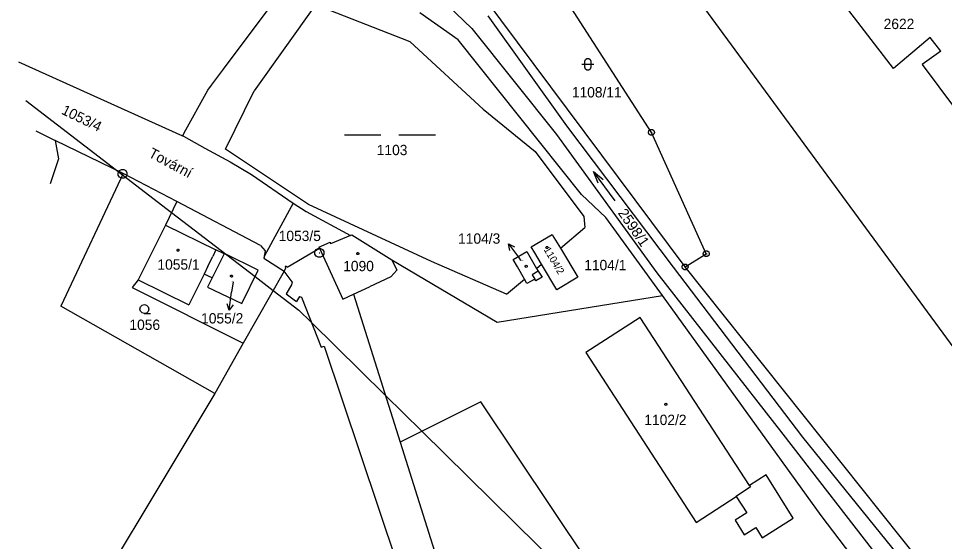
# Model space of a CAD drawing. Extents: x -806774 to -803680, y -1151731 to -1150053.
# Drawn here: x -804231.2 to -804078.6, y -1150279.7 to -1150193.4 of the extents above; entities that cross this region are included whole.
import ezdxf

# ---------------------------------------------------------------- set-up
doc = ezdxf.new("R2010")
doc.units = 0
for name, color, linetype in [('1', 7, 'Continuous'), ('11', 7, 'Continuous'), ('12', 7, 'Continuous'), ('2', 7, 'Continuous'), ('3', 7, 'Continuous'), ('4', 7, 'Continuous'), ('5', 7, 'Continuous'), ('7', 7, 'Continuous'), ('8', 7, 'Continuous')]:
    doc.layers.add(name, color=color, linetype=linetype)

msp = doc.modelspace()

# ---------------------------------------------------------------- linework, layer by layer
at = {"layer": '1'}
for p, q in [((-804126.9, -1150212.23), (-804145.58, -1150183.24)), ((-804197.45, -1150201.82), (-804184.26, -1150184.19)), ((-804121.35, -1150234.4), (-804156.46, -1150187.28)), ((-804087, -1150201.67), (-804097.02, -1150188.64)), ((-804182.27, -1150191.21), (-804192.39, -1150205.34)), ((-804166.66, -1150197.27), (-804182.27, -1150191.21)), ((-804158.76, -1150196.95), (-804165.08, -1150192.52)), ((-804166.66, -1150197.27), (-804154.63, -1150208.39)), ((-804138.44, -1150222.48), (-804158.76, -1150196.95)), ((-804080.94, -1150196.58), (-804087, -1150201.67)), ((-804079.2, -1150198.82), (-804080.94, -1150196.58)), ((-804079.2, -1150198.82), (-804082.27, -1150201.05)), ((-804231.23, -1150200.58), (-804204.2, -1150212.78)), ((-804199.4, -1150204.43), (-804197.45, -1150201.82)), ((-804082.27, -1150201.05), (-804076.76, -1150208.41)), ((-804203.9, -1150212.27), (-804200.03, -1150205.28)), ((-804200.03, -1150205.28), (-804199.4, -1150204.43)), ((-804197.12, -1150214.97), (-804192.39, -1150205.34)), ((-804154.63, -1150208.39), (-804146.05, -1150215.39)), ((-804228.4, -1150211.95), (-804225.21, -1150213.58)), ((-804203.9, -1150212.27), (-804204.2, -1150212.78)), ((-804204.2, -1150212.78), (-804204.05, -1150212.85)), ((-804204.05, -1150212.85), (-804200.51, -1150214.79)), ((-804117.86, -1150232.22), (-804126.9, -1150212.23)), ((-804225.21, -1150213.58), (-804224.63, -1150216.55)), ((-804213.98, -1150218.97), (-804225.21, -1150213.58)), ((-804200.51, -1150214.79), (-804196.34, -1150217.06)), ((-804183.44, -1150224.11), (-804197.12, -1150214.97)), ((-804146.05, -1150215.39), (-804138.03, -1150226.06)), ((-804224.63, -1150216.55), (-804226, -1150220.72)), ((-804196.34, -1150217.06), (-804192.85, -1150219.16)), ((-804213.98, -1150218.97), (-804224.25, -1150240.88)), ((-804205.16, -1150223.61), (-804213.98, -1150218.97)), ((-804192.85, -1150219.16), (-804185.95, -1150223.88)), ((-804205.16, -1150223.61), (-804206.99, -1150227.5)), ((-804191.34, -1150230.88), (-804205.16, -1150223.61)), ((-804134.41, -1150226.23), (-804138.44, -1150222.48)), ((-804185.95, -1150223.88), (-804190.68, -1150232.58)), ((-804185.95, -1150223.88), (-804183.81, -1150225.26)), ((-804183.81, -1150225.26), (-804176.51, -1150229.21)), ((-804163.17, -1150233.5), (-804183.44, -1150224.11)), ((-804138.03, -1150226.06), (-804137.9, -1150227.9)), ((-804125.07, -1150239.09), (-804134.41, -1150226.23)), ((-804206.99, -1150227.5), (-804211.52, -1150236.54)), ((-804141.9, -1150231.32), (-804137.9, -1150227.9)), ((-804176.51, -1150229.21), (-804179.78, -1150230.61)), ((-804176.51, -1150229.21), (-804176.28, -1150229.11)), ((-804176.28, -1150229.11), (-804169.72, -1150233.25)), ((-804146.72, -1150231.08), (-804143.27, -1150229.04)), ((-804143.27, -1150229.04), (-804142.98, -1150229.52)), ((-804142.98, -1150229.52), (-804141.9, -1150231.32)), ((-804191.34, -1150230.88), (-804190.6, -1150231.74)), ((-804186.96, -1150234.45), (-804181.64, -1150231.33)), ((-804181.72, -1150231.15), (-804179.84, -1150230.31)), ((-804181.72, -1150231.15), (-804181.64, -1150231.33)), ((-804181.64, -1150231.33), (-804177.76, -1150239.69)), ((-804179.84, -1150230.31), (-804179.78, -1150230.61)), ((-804146.13, -1150232.06), (-804146.72, -1150231.08)), ((-804141.9, -1150231.32), (-804139.01, -1150236.11)), ((-804197.31, -1150232.21), (-804199.31, -1150236.18)), ((-804197.3, -1150232.19), (-804197.31, -1150232.21)), ((-804191.7, -1150234.93), (-804197.3, -1150232.19)), ((-804190.6, -1150231.74), (-804190.81, -1150232.94)), ((-804190.68, -1150232.58), (-804190.81, -1150232.94)), ((-804149.69, -1150233.15), (-804147.45, -1150231.88)), ((-804147.45, -1150231.88), (-804146.95, -1150232.73)), ((-804146.95, -1150232.73), (-804145.82, -1150234.66)), ((-804145, -1150233.96), (-804146.13, -1150232.06)), ((-804121.35, -1150234.4), (-804117.86, -1150232.22)), ((-804190.81, -1150232.94), (-804187.42, -1150235.07)), ((-804187.1, -1150234.28), (-804187.25, -1150234.4)), ((-804187.25, -1150234.4), (-804187.2, -1150234.6)), ((-804186.96, -1150234.45), (-804187.1, -1150234.28)), ((-804169.72, -1150233.25), (-804168.87, -1150234.95)), ((-804169.72, -1150233.25), (-804152.35, -1150243.49)), ((-804150.79, -1150238.91), (-804163.17, -1150233.5)), ((-804148.99, -1150234.38), (-804149.69, -1150233.15)), ((-804147.85, -1150236.4), (-804148.99, -1150234.38)), ((-804145.82, -1150234.66), (-804145, -1150233.96)), ((-804142.49, -1150238.15), (-804145, -1150233.96)), ((-804081.21, -1150284.7), (-804121.35, -1150234.4)), ((-804194.4, -1150240.45), (-804191.7, -1150234.93)), ((-804187.42, -1150235.07), (-804194.18, -1150246.99)), ((-804187.2, -1150234.6), (-804187.42, -1150235.07)), ((-804186.12, -1150236.84), (-804187.42, -1150235.07)), ((-804168.87, -1150234.95), (-804169.87, -1150236.05)), ((-804145.82, -1150234.66), (-804145.55, -1150235.12)), ((-804145.55, -1150235.12), (-804144.92, -1150236.11)), ((-804211.52, -1150236.54), (-804212.49, -1150237.81)), ((-804199.31, -1150236.18), (-804200.07, -1150237.74)), ((-804186.21, -1150237.35), (-804187.12, -1150238.84)), ((-804186.12, -1150236.84), (-804186.21, -1150237.35)), ((-804169.87, -1150236.05), (-804173.37, -1150237.66)), ((-804150.79, -1150238.91), (-804147.85, -1150236.4)), ((-804147.43, -1150237.14), (-804147.85, -1150236.4)), ((-804146.14, -1150236.42), (-804147.43, -1150237.14)), ((-804145.97, -1150236.71), (-804146.14, -1150236.42)), ((-804144.92, -1150236.11), (-804145.97, -1150236.71)), ((-804139.01, -1150236.11), (-804142.49, -1150238.15)), ((-804212.49, -1150237.81), (-804194.18, -1150246.99)), ((-804200.07, -1150237.74), (-804194.4, -1150240.45)), ((-804187.12, -1150238.84), (-804186.69, -1150239.16)), ((-804177.76, -1150239.69), (-804176.03, -1150238.89)), ((-804176.03, -1150238.89), (-804173.37, -1150237.66)), ((-804176.03, -1150238.89), (-804168.33, -1150263.26)), ((-804186.69, -1150239.16), (-804185.81, -1150239.81)), ((-804185.81, -1150239.81), (-804185.41, -1150240.11)), ((-804184.91, -1150239.25), (-804185.41, -1150240.11)), ((-804184.91, -1150239.25), (-804184.57, -1150239.39)), ((-804184.57, -1150239.39), (-804181.35, -1150247.65)), ((-804152.35, -1150243.49), (-804125.07, -1150239.09)), ((-804098.91, -1150275.35), (-804125.07, -1150239.09)), ((-804198.87, -1150255.25), (-804224.25, -1150240.88)), ((-804128.74, -1150242.73), (-804137.71, -1150248.5)), ((-804110.74, -1150270.45), (-804128.74, -1150242.73)), ((-804194.18, -1150246.99), (-804198.87, -1150255.25)), ((-804181.35, -1150247.65), (-804180.87, -1150247.45)), ((-804180.87, -1150247.45), (-804164.62, -1150295.77)), ((-804137.71, -1150248.5), (-804119.52, -1150276.54)), ((-804198.87, -1150255.25), (-804209.11, -1150272.3)), ((-804155.03, -1150256.65), (-804165.04, -1150261.63)), ((-804116.64, -1150313.9), (-804155.03, -1150256.65)), ((-804165.04, -1150261.63), (-804168.33, -1150263.26)), ((-804168.33, -1150263.26), (-804152.34, -1150313.77)), ((-804108.01, -1150268.68), (-804110.74, -1150270.45)), ((-804103.54, -1150275.84), (-804108.01, -1150268.68)), ((-804209.11, -1150272.3), (-804220.9, -1150291.91)), ((-804119.52, -1150276.54), (-804112.91, -1150272.23)), ((-804112.91, -1150272.23), (-804111.15, -1150274.93)), ((-804111.15, -1150274.93), (-804113.12, -1150276.17)), ((-804036.11, -1150358.19), (-804098.91, -1150275.35)), ((-804113.12, -1150276.17), (-804111.63, -1150278.57)), ((-804108.65, -1150279.08), (-804103.54, -1150275.84)), ((-804111.63, -1150278.57), (-804109.69, -1150277.35)), ((-804109.69, -1150277.35), (-804108.65, -1150279.08))]:
    msp.add_line(p, q, dxfattribs=at)
at = {"layer": '11'}
for points in [[(-804075, -1150250.5), (-804130.24, -1150175.18), (-804140.05, -1150161.79), (-804142.89, -1150157.92)], [(-804230.04, -1150206.98), (-804215.07, -1150218.45), (-804214.09, -1150219.2), (-804206, -1150225.4), (-804196.87, -1150232.4), (-804192.21, -1150235.97), (-804189.23, -1150238.26), (-804185, -1150241.5), (-804182.97, -1150243.51), (-804170.77, -1150255.53), (-804164.74, -1150261.48), (-804126.52, -1150299.17), (-804113, -1150312.5), (-804105.14, -1150321.67), (-804088.1, -1150341.55)]]:
    msp.add_lwpolyline(points, dxfattribs=at)
at = {"layer": '12'}
for p, q in [((-804206.99, -1150227.5), (-804211.52, -1150236.54)), ((-804206.99, -1150227.5), (-804198.68, -1150231.59)), ((-804176.51, -1150229.21), (-804179.78, -1150230.61)), ((-804176.51, -1150229.21), (-804176.28, -1150229.11)), ((-804176.28, -1150229.11), (-804169.72, -1150233.25)), ((-804146.72, -1150231.08), (-804143.27, -1150229.04)), ((-804143.27, -1150229.04), (-804142.98, -1150229.52)), ((-804142.98, -1150229.52), (-804141.9, -1150231.32)), ((-804181.72, -1150231.15), (-804179.84, -1150230.31)), ((-804181.72, -1150231.15), (-804181.64, -1150231.33)), ((-804181.64, -1150231.33), (-804177.76, -1150239.69)), ((-804179.84, -1150230.31), (-804179.78, -1150230.61)), ((-804146.13, -1150232.06), (-804146.72, -1150231.08)), ((-804141.9, -1150231.32), (-804139.01, -1150236.11)), ((-804200, -1150234.26), (-804199.22, -1150232.68)), ((-804197.31, -1150232.21), (-804199.31, -1150236.18)), ((-804198.68, -1150231.59), (-804199.22, -1150232.68)), ((-804197.3, -1150232.19), (-804197.31, -1150232.21)), ((-804191.7, -1150234.93), (-804197.3, -1150232.19)), ((-804149.69, -1150233.15), (-804147.45, -1150231.88)), ((-804147.45, -1150231.88), (-804146.95, -1150232.73)), ((-804146.95, -1150232.73), (-804145.82, -1150234.66)), ((-804145, -1150233.96), (-804146.13, -1150232.06)), ((-804200, -1150234.26), (-804200.64, -1150235.59)), ((-804169.72, -1150233.25), (-804168.87, -1150234.95)), ((-804148.99, -1150234.38), (-804149.69, -1150233.15)), ((-804147.85, -1150236.4), (-804148.99, -1150234.38)), ((-804142.49, -1150238.15), (-804145, -1150233.96)), ((-804200.64, -1150235.59), (-804203.16, -1150240.67)), ((-804194.4, -1150240.45), (-804191.7, -1150234.93)), ((-804168.87, -1150234.95), (-804169.87, -1150236.05)), ((-804145.55, -1150235.12), (-804146.56, -1150235.7)), ((-804146.56, -1150235.7), (-804146.14, -1150236.42)), ((-804145.82, -1150234.66), (-804145.55, -1150235.12)), ((-804211.52, -1150236.54), (-804203.16, -1150240.67)), ((-804199.31, -1150236.18), (-804200.07, -1150237.74)), ((-804169.87, -1150236.05), (-804173.37, -1150237.66)), ((-804147.43, -1150237.14), (-804147.85, -1150236.4)), ((-804146.14, -1150236.42), (-804147.43, -1150237.14)), ((-804139.01, -1150236.11), (-804142.49, -1150238.15)), ((-804200.07, -1150237.74), (-804194.4, -1150240.45)), ((-804177.76, -1150239.69), (-804176.03, -1150238.89)), ((-804176.03, -1150238.89), (-804173.37, -1150237.66)), ((-804128.74, -1150242.73), (-804137.71, -1150248.5)), ((-804110.74, -1150270.45), (-804128.74, -1150242.73)), ((-804137.71, -1150248.5), (-804119.52, -1150276.54)), ((-804110.57, -1150270.67), (-804112.91, -1150272.23)), ((-804110.74, -1150270.45), (-804110.57, -1150270.67)), ((-804119.52, -1150276.54), (-804112.91, -1150272.23))]:
    msp.add_line(p, q, dxfattribs=at)
at = {"layer": '3'}
for p, q in [((-804177.52, -1150212.62), (-804171.52, -1150212.62)), ((-804168.52, -1150212.62), (-804162.52, -1150212.62)), ((-804132.87, -1150223.48), (-804136.47, -1150218.68))]:
    msp.add_line(p, q, dxfattribs=at)
msp.add_lwpolyline([(-804137.89, -1150200.48), (-804137.79, -1150200.19), (-804137.54, -1150200.01), (-804137.23, -1150200.01), (-804136.98, -1150200.19), (-804136.88, -1150200.48), (-804136.88, -1150201.48), (-804136.98, -1150201.77), (-804137.23, -1150201.95), (-804137.54, -1150201.95), (-804137.79, -1150201.77), (-804137.89, -1150201.48)], close=True, dxfattribs=at)
for points in [[(-804138.39, -1150200.98), (-804137.12, -1150200.98), (-804136.39, -1150200.98)], [(-804135.67, -1150220.58), (-804136.47, -1150218.68), (-804134.87, -1150219.98)], [(-804210.48, -1150242.08), (-804210.86, -1150241.98), (-804211.13, -1150241.71), (-804211.23, -1150241.34), (-804211.13, -1150240.97), (-804210.86, -1150240.7), (-804210.49, -1150240.6), (-804210.12, -1150240.7), (-804209.85, -1150240.97), (-804209.75, -1150241.35), (-804209.85, -1150241.73), (-804210.12, -1150242), (-804210.5, -1150242.1), (-804209.5, -1150242.1)]]:
    msp.add_lwpolyline(points, dxfattribs=at)
at = {"layer": '4'}
for p, q in [((-804156.49, -1150195.07), (-804164.28, -1150187.59)), ((-804140.87, -1150211.16), (-804153.84, -1150192.99)), ((-804156.49, -1150195.07), (-804142.53, -1150212.59)), ((-804123.25, -1150234.46), (-804140.87, -1150211.16)), ((-804142.53, -1150212.59), (-804126, -1150235.35)), ((-804206.99, -1150227.5), (-804198.68, -1150231.59)), ((-804200, -1150234.26), (-804199.22, -1150232.68)), ((-804198.68, -1150231.59), (-804199.22, -1150232.68)), ((-804197.31, -1150232.21), (-804198.68, -1150231.59)), ((-804200, -1150234.26), (-804200.64, -1150235.59)), ((-804101.97, -1150262.44), (-804123.25, -1150234.46)), ((-804200.64, -1150235.59), (-804203.16, -1150240.67)), ((-804199.31, -1150236.18), (-804200.64, -1150235.59)), ((-804145.55, -1150235.12), (-804146.56, -1150235.7)), ((-804146.56, -1150235.7), (-804146.14, -1150236.42)), ((-804126, -1150235.35), (-804105.26, -1150261.99)), ((-804211.52, -1150236.54), (-804203.16, -1150240.67)), ((-804105.26, -1150261.99), (-804080.36, -1150294)), ((-804083.56, -1150285.18), (-804101.97, -1150262.44)), ((-804110.57, -1150270.67), (-804112.91, -1150272.23)), ((-804110.74, -1150270.45), (-804110.57, -1150270.67))]:
    msp.add_line(p, q, dxfattribs=at)
at = {"layer": '5'}
for points in [[(-804143.98, -1150231.1), (-804143.95, -1150231.2), (-804144, -1150231.29), (-804144.04, -1150231.34), (-804144.13, -1150231.36), (-804144.23, -1150231.33), (-804144.28, -1150231.28), (-804144.3, -1150231.18), (-804144.28, -1150231.1), (-804144.22, -1150231.04), (-804144.13, -1150231.02), (-804144.03, -1150231.05)], [(-804204.93, -1150231.48), (-804204.83, -1150231.5), (-804204.78, -1150231.59), (-804204.76, -1150231.65), (-804204.78, -1150231.74), (-804204.86, -1150231.81), (-804204.93, -1150231.82), (-804205.02, -1150231.79), (-804205.08, -1150231.73), (-804205.1, -1150231.65), (-804205.08, -1150231.56), (-804205, -1150231.49)], [(-804175.31, -1150232.03), (-804175.21, -1150232.05), (-804175.16, -1150232.14), (-804175.14, -1150232.2), (-804175.16, -1150232.29), (-804175.24, -1150232.36), (-804175.31, -1150232.37), (-804175.4, -1150232.34), (-804175.46, -1150232.28), (-804175.48, -1150232.2), (-804175.46, -1150232.11), (-804175.38, -1150232.04)], [(-804147.39, -1150234.21), (-804147.36, -1150234.31), (-804147.41, -1150234.4), (-804147.45, -1150234.45), (-804147.54, -1150234.47), (-804147.64, -1150234.44), (-804147.69, -1150234.39), (-804147.71, -1150234.29), (-804147.69, -1150234.21), (-804147.63, -1150234.15), (-804147.54, -1150234.13), (-804147.44, -1150234.16)], [(-804196.11, -1150235.73), (-804196.01, -1150235.75), (-804195.96, -1150235.84), (-804195.94, -1150235.9), (-804195.96, -1150235.99), (-804196.04, -1150236.06), (-804196.11, -1150236.07), (-804196.2, -1150236.04), (-804196.26, -1150235.98), (-804196.28, -1150235.9), (-804196.26, -1150235.81), (-804196.18, -1150235.74)], [(-804124.52, -1150256.88), (-804124.42, -1150256.9), (-804124.37, -1150256.99), (-804124.35, -1150257.05), (-804124.37, -1150257.14), (-804124.45, -1150257.21), (-804124.52, -1150257.22), (-804124.61, -1150257.19), (-804124.67, -1150257.13), (-804124.69, -1150257.05), (-804124.67, -1150256.96), (-804124.59, -1150256.89)]]:
    msp.add_lwpolyline(points, close=True, dxfattribs=at)
at = {"layer": '7'}
for p, q in [((-804150.45, -1150230.57), (-804148.67, -1150232.99)), ((-804148.4, -1150233.36), (-804148.67, -1150232.99)), ((-804195.87, -1150236.86), (-804196.1, -1150238.58)), ((-804196.5, -1150241.55), (-804196.1, -1150238.58))]:
    msp.add_line(p, q, dxfattribs=at)
for points in [[(-804150.26, -1150231.67), (-804150.45, -1150230.57), (-804149.45, -1150231.08)], [(-804195.87, -1150240.63), (-804196.5, -1150241.55), (-804196.86, -1150240.5)]]:
    msp.add_lwpolyline(points, dxfattribs=at)
at = {"layer": '8'}
for p, q in [((-804127.02, -1150212.23), (-804126.78, -1150212.23)), ((-804214.12, -1150219.05), (-804214.02, -1150219.05)), ((-804181.68, -1150232.07), (-804181.58, -1150232.07)), ((-804117.98, -1150232.22), (-804117.74, -1150232.22)), ((-804121.47, -1150234.4), (-804121.23, -1150234.4))]:
    msp.add_line(p, q, dxfattribs=at)
for points in [[(-804126.75, -1150211.75), (-804126.5, -1150211.93), (-804126.4, -1150212.22), (-804126.5, -1150212.51), (-804126.75, -1150212.69), (-804127.06, -1150212.69), (-804127.31, -1150212.51), (-804127.41, -1150212.22), (-804127.31, -1150211.93), (-804127.06, -1150211.75)], [(-804213.88, -1150218.33), (-804213.54, -1150218.52), (-804213.35, -1150218.86), (-804213.35, -1150219.25), (-804213.54, -1150219.59), (-804213.88, -1150219.78), (-804214.27, -1150219.78), (-804214.61, -1150219.59), (-804214.8, -1150219.25), (-804214.8, -1150218.86), (-804214.61, -1150218.52), (-804214.27, -1150218.33)], [(-804181.44, -1150231.35), (-804181.1, -1150231.54), (-804180.91, -1150231.88), (-804180.91, -1150232.27), (-804181.1, -1150232.61), (-804181.44, -1150232.8), (-804181.83, -1150232.8), (-804182.17, -1150232.61), (-804182.36, -1150232.27), (-804182.36, -1150231.88), (-804182.17, -1150231.54), (-804181.83, -1150231.35)], [(-804117.71, -1150231.74), (-804117.46, -1150231.92), (-804117.36, -1150232.21), (-804117.46, -1150232.5), (-804117.71, -1150232.68), (-804118.02, -1150232.68), (-804118.27, -1150232.5), (-804118.37, -1150232.21), (-804118.27, -1150231.92), (-804118.02, -1150231.74)], [(-804121.2, -1150233.92), (-804120.95, -1150234.1), (-804120.85, -1150234.39), (-804120.95, -1150234.68), (-804121.2, -1150234.86), (-804121.51, -1150234.86), (-804121.76, -1150234.68), (-804121.86, -1150234.39), (-804121.76, -1150234.1), (-804121.51, -1150233.92)]]:
    msp.add_lwpolyline(points, close=True, dxfattribs=at)

# ---------------------------------------------------------------- texts
at = {"layer": '2'}
for s, height, p in [('2622', 1.7, (-804088.62, -1150195.18)), ('1108/11', 1.7, (-804140.02, -1150206.45)), ('1103', 1.7, (-804172.18, -1150215.97)), ('1053/5', 1.7, (-804188.34, -1150230.13)), ('1055/1', 1.7, (-804208.33, -1150234.85)), ('1090', 1.7, (-804177.71, -1150235.1)), ('1104/3', 0.1, (-804148.38, -1150233.36)), ('1104/1', 1.7, (-804137.98, -1150234.94)), ('1055/2', 0.1, (-804196.1, -1150236.86)), ('1056', 1.7, (-804212.95, -1150244.78)), ('1102/2', 1.7, (-804128.07, -1150260.46))]:
    msp.add_text(s, height=height, dxfattribs=at).set_placement(p)
for s, height, rotation, p in [('1053/4', 1.7, 333.9198, (-804224.29, -1150209.1)), ('2598/1', 1.7, 304.699, (-804132.49, -1150225.51)), ('1104/2', 1.2, 300.5737, (-804144.71, -1150231.54))]:
    msp.add_text(s, height=height, rotation=rotation, dxfattribs=at).set_placement(p)
at = {"layer": '7'}
msp.add_text('Tovární', height=1.7, rotation=331.8572, dxfattribs=at).set_placement((-804209.94, -1150216.17))
for s, p in [('1104/3', (-804158.77, -1150230.57)), ('1055/2', (-804201.13, -1150243.72))]:
    msp.add_text(s, height=1.7, dxfattribs=at).set_placement(p)

doc.saveas('drawing.dxf')
